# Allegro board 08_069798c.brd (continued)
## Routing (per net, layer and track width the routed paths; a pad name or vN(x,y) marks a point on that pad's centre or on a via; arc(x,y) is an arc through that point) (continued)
DA_P: length 65.8
  TOP w0.127: v1(73.97,33.04) 73.7,32.77 73.31,32.77 71.96,34.11 71.53,34.11 71.34,34.3 U8.C7
  L3_PRIMARY_POWER w0.127: v1(88.05,48.75) 88.39,48.41 88.39,46.38 89.15,45.62 95.89,45.62 96.5,45.01 96.5,42.1 96.02,41.62 92.58,41.62 92.29,41.33 92.29,40.13 92.58,39.84 95.04,39.84 95.95,38.93 95.95,36.58 94.14,34.77 90.23,34.77 88.54,36.46 86.61,36.46 86.19,36.04 86.19,34.82 87.88,33.13 87.88,32.7 87.75,32.57 87.38,32.57 v2(86.55,33.4) 85.61,32.46 81.23,32.46 80.91,32.14 78.51,32.14 77.95,32.7 74.31,32.7 v1(73.97,33.04)
  BOTTOM w0.127: v1(88.05,48.75) 88.39,49.09 88.39,49.73 90,51.35 91.12,51.35 91.24,51.47 P3.H7
DB_N: length 45
  L3_PRIMARY_POWER w0.127: v1(93.5,47.54) 93.84,47.88 93.84,48.06 93.71,48.18 90.39,48.18 89.25,49.32 87.41,49.32 85.97,47.89 85.97,45.26 86.15,45.09 87,45.09 88.41,43.68 88.41,43.19 87.84,42.61 87.5,42.61 v2(86.55,41.66) 85.59,42.61 83.82,42.61 82.95,41.74 79.65,41.74 79.04,41.13 79.04,35.55 78.09,34.59 74.34,34.59 v1(74.02,34.27)
  BOTTOM w0.127: P3.G10 92.51,48.4 92.64,48.53 93.67,48.53 93.83,48.36 93.83,47.87 v1(93.5,47.54) ; v1(74.02,34.27) 73.71,34.59 72.12,34.59 71.37,33.84 70.95,33.84 70.77,33.66 v2(70.32,33.66)
DB_P: length 45.9
  L3_PRIMARY_POWER w0.127: v1(94.46,47.56) 94.12,47.9 94.12,48.17 93.83,48.46 90.51,48.46 89.37,49.6 87.29,49.6 85.69,48.01 85.69,45.15 86.03,44.81 86.89,44.81 88.13,43.56 88.13,43.31 87.75,42.93 87.47,42.93 v2(86.55,43.85) 85.59,42.89 83.71,42.89 82.84,42.02 79.53,42.02 78.76,41.25 78.76,35.66 77.97,34.87 74.34,34.87 v1(74.02,35.19)
  BOTTOM w0.127: v1(94.46,47.56) 94.11,47.91 94.11,48.48 93.78,48.81 92.64,48.81 92.51,48.93 P3.G9 ; v2(70.32,34.3) 70.77,34.3 70.95,34.12 71.25,34.12 72,34.87 73.71,34.87 v1(74.02,35.19)
DCO_N: length 45.7
  L3_PRIMARY_POWER w0.127: v1(68.88,44.88) 69.2,45.2 69.2,46.24 69.82,46.85 69.82,51.48 71.45,53.11 74.02,53.11 75.18,51.95 78.22,51.95 78.87,52.6 80.27,52.6 84.25,56.58 87.56,56.58 89.76,54.38 91.26,54.38 91.54,54.66 91.54,55.32 91.41,55.45 90.85,55.45 90.7,55.3 v1(90.7,54.93)
  BOTTOM w0.127: v2(69.02,34.95) 69.02,35.4 69.2,35.59 69.2,44.55 v1(68.88,44.88)
  BOTTOM w0.203: P3.H5 v1(90.7,54.93)
DCO_P: length 46.1
  L3_PRIMARY_POWER w0.127: v1(69.83,44.88) 69.48,45.23 69.48,46.12 70.1,46.74 70.1,51.37 71.56,52.83 73.91,52.83 75.07,51.67 78.34,51.67 78.99,52.32 80.39,52.32 84.36,56.3 87.45,56.3 89.64,54.1 91.37,54.1 91.82,54.55 91.82,55.44 91.53,55.73 90.82,55.73 90.7,55.86 v1(90.7,56.2)
  BOTTOM w0.127: v1(69.83,44.88) 69.48,44.53 69.48,35.59 69.67,35.4 v2(69.67,34.95)
  BOTTOM w0.203: P3.H4 v1(90.7,56.2)
DOA: length 4.8
  TOP w0.203: JP10.2 84.64,34.26 84.84,34.47 87.53,34.47 87.94,34.87 U4.4
DOA_FMC: length 14.8
  TOP w0.203: U4.3 v1(86.99,35.29)
  L3_PRIMARY_POWER w0.127: v1(86.99,35.29) 87.42,34.86 87.42,34.53 89.68,32.27 92.58,32.27 92.99,32.68 93.49,32.68 96.2,35.38 96.75,35.38 96.87,35.51 v1(96.87,35.88)
  BOTTOM w0.203: P3.D20 v1(96.87,35.88)
DOB: length 4.2
  TOP w0.203: JP11.2 88.45,30.04 88.26,29.85 86.23,29.85 86.04,29.66 U5.4
DOB_FMC: length 14.6
  TOP w0.203: U5.3 v1(86.99,29.22)
  L3_PRIMARY_POWER w0.127: v1(86.99,29.22) 87.49,29.72 87.49,29.89 89.58,31.99 92.69,31.99 93.1,32.4 93.61,32.4 96.31,35.1 96.75,35.1 96.87,34.98 v1(96.87,34.61)
  BOTTOM w0.203: P3.D21 v1(96.87,34.61)
DOC: length 5.2
  TOP w0.203: JP12.2 84.64,44.86 84.87,45.09 87.75,45.09 87.94,45.27 U6.4
DOC_FMC: length 15.8
  TOP w0.203: U6.3 v1(86.99,45.96)
  L3_PRIMARY_POWER w0.127: v1(93.94,37.71) 93.6,37.38 93.02,37.38 90.06,40.33 90.06,42.65 89.77,42.94 89.28,42.94 89.15,43.07 89.15,44.58 87.77,45.96 v1(86.99,45.96)
  BOTTOM w0.127: P3.G18 92.51,37.5 92.64,37.38 93.6,37.38 v1(93.94,37.71)
DOD: length 4.2
  TOP w0.203: U7.4 86.04,40.2 86.23,40.39 88.18,40.39 88.45,40.65 JP13.2
DOD_FMC: length 15.6
  TOP w0.203: U7.3 v1(86.99,39.64)
  L3_PRIMARY_POWER w0.127: v1(93.94,36.76) 93.6,37.1 92.91,37.1 89.78,40.22 89.78,42.53 89.66,42.66 89.28,42.66 89.15,42.53 89.15,41.4 87.39,39.64 v1(86.99,39.64)
  BOTTOM w0.127: P3.G19 92.51,36.97 92.64,37.1 93.6,37.1 v1(93.94,36.76)
EC0: length 1.9
  BOTTOM w0.203: C70.1 74.41,58.28 74.25,58.11 U20.5
EC1: length 2.1
  BOTTOM w0.203: C69.1 74.25,51.54 U20.14
EN1V1: length 7.5
  TOP w0.203: 14.52,51.16 14.53,51.16 14.53,46.6 P5.2 ; 14.52,51.16 R20.2 ; 14.52,51.16 14.52,51.96 U35.4
EN_AFE: length 127.4
  TOP w0.203: U27.2 v1(18.85,14.72) ; U25.1 65.66,17.32 v1(66.85,17.32) 67.67,17.32 68.24,16.75 68.24,12.05 67.74,11.54 v1(66.78,11.54) 65.67,11.54 U36.3 ; U26.2 v1(14.28,14.77) ; U3.12 38.15,33.77 v1(38.41,34.04) ; v1(70.72,23.86) 69.7,23.86 U39.5 ; U28.1 v1(22.76,14.84) ; U23.4 77.84,4.78 78.31,4.3 79.23,4.3 80.13,5.21 v1(80.13,9)
  L3_PRIMARY_POWER w0.203: v1(70.72,23.86) 70.72,21.19 v1(66.85,17.32)
  BOTTOM w0.203: v1(66.78,11.54) 67.41,11.54 68.82,10.13 68.82,9.3 70.56,7.55 72.9,7.55 73.63,8.29 73.85,8.29 74.56,9 v1(80.13,9) ; v1(70.72,23.86) 66.59,23.86 59.93,30.53 47.57,30.53 P2.4 43.34,33.02 42.32,34.04 v1(38.41,34.04) 38.41,32.99 41,30.4 41,25.91 40.8,25.7 39.85,25.7 39.85,25.7 39.39,25.7 39.38,25.7 30.72,25.7 27.92,22.91 27.92,20.56 26.14,18.78 23.73,18.78 23.48,18.53 23.48,15.55 v1(22.76,14.84) 22.71,14.84 22.08,14.21 19.36,14.21 v1(18.85,14.72) 16.43,14.72 16.05,14.34 14.72,14.34 v1(14.28,14.77)
EN_PSU: length 77
  TOP w0.203: v1(90.48,36.49) 89.9,35.91 89.9,32.62 91.43,31.09 91.43,25.78 84.44,18.78 v1(84.44,18.21)
  L5_SECONDARY_POWER w0.203: v1(38.47,18.59) 38.47,20.76 39.73,22.02 41.83,22.02 43.67,20.18 50.38,20.18 50.7,20.5 51.67,20.5 52.06,20.11 82.53,20.11 v1(84.44,18.21)
  BOTTOM w0.203: P3.H19 90.89,36.6 90.78,36.49 v1(90.48,36.49)
  BOTTOM w0.254: U38.2 83.23,18.52 R133.2 83.68,18.21 v1(84.44,18.21)
  BOTTOM w0.508: v1(38.47,18.59) U19.3
EN_V33: length 33.1
  TOP w0.203: U24.4 72.76,4.05 70.47,1.76 58.97,1.76 55.8,4.94 55.8,8.4 v1(58.42,11.02) ; v1(59.8,14.72) 58.52,14.72 U21.4
  L3_PRIMARY_POWER w0.203: v1(58.42,11.02) 59.8,12.4 v1(59.8,14.72)
EN_VDDLDO: length 8
  TOP w0.203: P12.2 28.56,50.97 R19.2 27.8,51.36 28.28,51.84 U33.4
ENS1N: length 6.6
  TOP w0.203: U27.4 v1(19.5,18.16) ; U2.5 v1(17.59,21.78)
  BOTTOM w0.203: v1(19.5,18.16) 18.88,18.78 18.02,18.78 17.59,19.21 v1(17.59,21.78)
ENS1P: length 23
  TOP w0.203: U1.5 v1(17.59,37.02) ; U26.4 v1(14.93,18.21)
  BOTTOM w0.203: v1(14.93,18.21) 14.93,19.32 13.32,20.94 13.32,27.73 17.59,32.01 v1(17.59,37.02)
ENS3: length 55.4
  TOP w0.203: A1.8 56.04,41.83 v1(56.74,42.53) ; A6.8 55.8,27.57 v1(55.8,28.32) ; U28.4 v1(24.06,18.16)
  L3_PRIMARY_POWER w0.203: v1(55.8,28.32) 55.48,28.64 55.48,42.14 55.87,42.53 v1(56.74,42.53)
  BOTTOM w0.203: v1(24.06,18.16) 26.1,18.16 28.37,20.43 28.37,22.72 30.84,25.19 41.13,25.19 42.72,26.78 48.88,26.78 50.41,28.32 v1(55.8,28.32)
ENVIO: length 2.3
  TOP w0.203: R35.2 41.95,50.9 42.88,51.84 U34.4
EXT_5V: length 5.7
  TOP w0.508: P8.1 28.87,5.48 ; P8.1 27.63,4.24 ; P8.1 28.87,2.99
  BOTTOM w0.508: JP24.1 29.38,15.16 27.88,15.16 v1(27.73,15.01)
  vias: v1(25.33,10.1) v1(25.33,9.33) v1(25.33,8.57) v1(25.97,10.1) v1(25.97,9.33) v1(25.97,8.57) v1(26.6,10.1) v1(26.6,9.33) v1(26.6,8.57)
EXT_M2V5: length 6.9
  TOP w0.508: 33.02,5.17 P8.3 ; P8.3 33.02,3.31 ; P8.3 34.89,3.31 ; P8.3 34.89,5.17
  BOTTOM w0.508: JP25.1 29.34,19.82 v1(29.07,19.82)
  vias: v1(35.36,10.1) v1(35.36,9.33) v1(35.36,8.57) v1(36,10.1) v1(36,9.33) v1(36,8.57) v1(36.63,10.1) v1(36.63,9.33) v1(36.63,8.57)
EXT_VDD1V1: length 1.8
  TOP w0.635: 30.78,64.82 30.78,63.04
EXT_VDD3V3: length 3.5
  TOP w0.508: P11.1 43.61,5.74 ; P11.1 42.43,4.56 ; P11.1 43.61,3.38
EXT_VDDLDO: length 1.8
  TOP w0.762: 35.86,64.82 35.86,63.04
EXT_VIO1V1: length 1.8
  TOP w0.762: P4.1 40.94,63.04
FDA5: length 4.3
  TOP w0.203: U3.5 35,30.94 v1(34.67,30.61)
  BOTTOM w0.508: v1(34.67,30.61) 34.68,30.59 R125.1
FDA8: length 6.1
  TOP w0.203: v1(36.83,30.61) 36.5,30.94 U3.8
  BOTTOM w0.508: v1(36.83,30.61) 37.8,30.61 38.98,29.43 38.98,28.28 R127.1
FDA13: length 4.1
  TOP w0.203: U3.13 36.5,35.1 v1(36.83,35.43)
  BOTTOM w0.508: v1(36.83,35.43) 36.83,37.66 R126.1
FDA16: length 4.4
  TOP w0.203: U3.16 35,35.1 v1(34.67,35.43)
  BOTTOM w0.508: R124.1 33.68,36.17 34.42,35.43 v1(34.67,35.43)
FDA_OB_N: length 2.5
  TOP w0.203: R102.1 39.08,33.27 U3.11
FDA_OB_P: length 2.6
  TOP w0.203: R103.1 38.99,32.77 U3.10
FDA_ON: length 37.7
  TOP w0.203: JP17.1 60.12,39.66 60.12,43.29 58.44,44.97 55.71,44.97 53.39,47.29 51,47.29 JP15.3 46.51,44.55 45.08,43.11 P2.1 43.81,40.64 43.23,40.05 43.23,34.3 42.74,33.82 C75.1 42.14,33.24 41.65,33.24 41.28,33.62 R102.2 R33.2
FDA_OP: length 33.2
  TOP w0.203: R18.2 R103.2 41.28,32.39 41.73,32.84 42.1,32.84 C75.2 42.74,32.22 43.23,31.74 43.23,26.08 43.91,25.4 P2.7 46.72,27.04 46.72,29.46 47.58,30.32 JP16.3 48.31,30.32 50.54,32.56 56.37,32.56 59.61,29.32 JP18.1
FFB: length 3.9
  TOP w0.203: R119.2 C122.1 60.93,48.59 60.7,48.81 R122.1
FMC_VADJ: length 34.7
  TOP w0.254: v1(89.8,27.93) C81.1 U5.1 ; v1(84.18,47.26) C82.1 U6.1 ; U24.5 73.87,6.47 73.9,6.5 C56.1 74.02,6.56 v1(74.02,7.35) ; v1(75.37,53.44) 75.37,52.88 C72.1 ; U26.5 v1(13.63,18.18) ; U27.5 v1(18.2,18.13) ; v1(67.97,57.28) R71.1 ; U28.5 v1(22.76,18.13) ; 84.7,36.59 C80.1 U4.1 ; U7.1 C83.1 v1(89.8,38.34) ; 78,6.63 U23.5
  TOP w0.305: v1(79.11,7.41) 79.17,7.36 C55.1 78.05,6.69 78,6.63 ; U9.6 C3.1 77.8,46.56 77.8,46.74 77.99,46.94 78.57,46.94 78.72,46.78 v1(78.85,46.78) ; v1(84.04,36.59) 84.7,36.59
  TOP w0.508: v1(69.32,4.05) R16.1 ; R55.1 v1(16.11,16.55) ; R56.1 v1(20.68,16.55) ; v1(71.86,8.55) R47.1 ; R53.1 v1(11.54,16.6) ; v1(73.53,9.07) R46.1
  L5_SECONDARY_POWER w0.508: P7.1 4.36,16.81 ; P7.1 2.59,15.04 ; P7.1 2.59,16.81 ; P7.1 4.36,15.04
  BOTTOM w0.203: P3.H40 v1(90.7,9.38) ; P3.G39 v1(91.97,10.65)
  BOTTOM w0.254: U11.5 v1(81.58,22.29) ; U12.5 v1(81.58,25.96) ; U20.6 v1(75.7,57.44) ; U20.13 v1(75.37,53.44) ; U13.5 v1(81.58,29.64)
  BOTTOM w0.508: R72.1 77.77,56.95 v1(77.77,57.64) ; v1(77.71,53.26) 77.71,53.92 R74.1
  vias: v1(79.91,42.63) v1(79.91,30.57) v1(80.29,46.31) v1(80.29,45.8) v1(80.29,38.95) v1(80.29,38.45) v1(80.29,35.28) v1(80.29,34.77) v1(80.29,27.41) v1(80.29,26.9) v1(80.29,23.73) v1(80.29,23.23) v1(80.42,42.63) v1(80.42,30.57)
FPGACLK_N: length 27
  L3_PRIMARY_POWER w0.127: v1(93.06,57.47) 93.06,57.84 92.94,57.96 91.12,57.96 89.25,59.83 86.52,59.83 85.01,58.32 76.54,58.32 74.17,60.68 73.27,60.68 73.14,60.55 73.14,60.28 v1(73.47,59.94)
  BOTTOM w0.127: v1(73.47,59.94) 73.14,59.61 73.14,58.33 73.25,58.22 U20.3 ; P3.G3 v1(93.06,57.47)
FPGACLK_P: length 27.5
  L3_PRIMARY_POWER w0.127: v1(93.06,58.74) 93.06,58.37 92.94,58.24 91.23,58.24 89.37,60.11 86.4,60.11 84.89,58.6 76.65,58.6 74.29,60.96 73.15,60.96 72.86,60.67 72.86,60.28 v1(72.52,59.94)
  BOTTOM w0.127: U20.2 72.75,58.22 72.86,58.33 72.86,59.61 v1(72.52,59.94) ; P3.G2 v1(93.06,58.74)
GA0: length 11.7
  TOP w0.203: v1(98.14,17) 97.58,16.44 97.58,13 97.14,12.56 96.72,12.56 96.02,11.86 93.61,11.86 93.02,12.44 U18.2
  BOTTOM w0.203: P3.C34 v1(98.14,17)
GA1: length 9.4
  TOP w0.203: v1(96.87,15.73) 96.87,16.29 96.66,16.5 91.8,16.5 91.41,16.1 91.41,15.01 91.75,14.67 U18.1
  BOTTOM w0.203: P3.D35 v1(96.87,15.73)
GP0_DIR: length 10.7
  BOTTOM w0.178: U14.5 81.58,41.02 81.81,41.25 85.4,41.25 86.23,40.42 91.23,40.42 P3.H16
GP1_DIR: length 25.9
  BOTTOM w0.178: U15.5 81.58,44.7 81.83,44.94 83.29,44.94 83.74,44.5 87.42,44.5 87.76,44.16 89.05,44.16 90.98,46.09 91.65,46.09 91.83,45.91 91.83,45.35 92.3,44.88 94.28,44.88 95.47,46.07 96.57,46.07 96.91,45.73 96.91,45.35 97.38,44.88 98.66,44.88 99.33,44.21 99.33,42.06 98.95,41.68 P3.C15
GP2_DIR: length 19.9
  BOTTOM w0.178: U16.5 81.58,33.66 81.74,33.83 84.05,33.83 84.25,34.02 87.1,34.02 89.01,35.93 89.01,36.78 90.35,38.11 90.35,38.24 90.56,38.45 91.55,38.45 91.83,38.73 91.83,39.32 92.3,39.79 94.04,39.79 94.22,39.97 94.22,41.32 93.86,41.68 P3.G15
GP3_DIR: length 12.2
  BOTTOM w0.178: U17.5 81.58,37.34 81.81,37.57 84.16,37.57 84.82,36.91 87.2,36.91 88.95,38.66 88.95,39.13 89.47,39.66 90.16,39.66 90.68,39.14 P3.H17
GPIO0: length 19.5
  TOP w0.178: U8.G7 71.11,31.84 71.36,31.84 71.67,31.53 v1(71.67,31.16)
  BOTTOM w0.178: U14.4 82.23,40.1 82.05,39.93 81.38,39.93 81,39.55 79.61,39.55 79.36,39.29 79.36,35.99 78.85,35.48 78.85,32.56 77.58,31.29 72.37,31.29 72.25,31.16 v1(71.67,31.16)
GPIO0_FMC: length 9.8
  BOTTOM w0.178: U14.3 88.34,42.37 90.19,44.22 P3.H13
GPIO1: length 20.5
  BOTTOM w0.178: U15.4 82.09,44.01 82.09,43.82 81.82,43.56 81.34,43.56 81.14,43.36 79.61,43.36 79.23,42.97 79.23,39.7 78.98,39.45 78.98,36.15 77.04,34.21 74.9,34.21 74.33,33.64 73.26,33.64 72.63,33.01 v2(70.32,33.01)
GPIO1_FMC: length 21.1
  BOTTOM w0.178: U15.3 82.9,46.05 84.01,44.94 86.66,44.94 87.13,45.41 89.77,45.41 90.6,46.24 90.6,47.03 90.99,47.42 91.42,47.42 91.87,46.98 91.87,46.53 92.22,46.18 94.21,46.18 95.11,47.07 95.11,48.3 95.42,48.61 96.57,48.61 97.01,48.17 97.01,47.79 97.59,47.2 P3.C11
GPIO2: length 22.2
  TOP w0.178: v1(65.9,32.05) 65.93,32.09 66.79,32.09 66.87,32.17 66.89,32.17 U8.F1
  BOTTOM w0.178: v1(65.9,32.05) 67.1,32.05 67.29,31.86 67.29,29.67 68.01,28.96 74.29,28.96 75.86,30.53 78.02,30.53 79.8,32.31 81.96,32.31 82.23,32.58 U16.4
GPIO2_FMC: length 30.8
  L3_PRIMARY_POWER w0.178: v1(88.63,37.39) 90.56,37.39 91.9,36.05 94.41,36.05 94.91,36.56 94.91,38.28 94.6,38.59 92.82,38.59 91.3,40.12 91.3,43.04 91.93,43.67 94.41,43.67 v1(95.73,42.35)
  BOTTOM w0.178: v1(88.63,37.39) 88.63,36.08 86.95,34.4 84.5,34.4 83.89,35.02 U16.3 ; P3.D14 v1(95.73,42.35)
GPIO3: length 22.2
  BOTTOM w0.178: U17.4 82.23,36.42 82.05,36.24 81.38,36.24 81.13,35.99 79.99,35.99 79.23,35.23 79.23,32.37 77.77,30.91 75.71,30.91 74.13,29.34 68.17,29.34 67.72,29.78 v2(67.72,32.36)
GPIO3_FMC: length 25.7
  BOTTOM w0.178: P3.D15 96.32,42.12 96.91,42.71 96.91,43.19 96.46,43.64 90.24,43.64 89.9,43.29 89.9,41.26 90.16,40.99 91.49,40.99 91.83,40.65 91.83,40.07 91.49,39.72 90.99,39.72 90.67,40.04 89.32,40.04 88.5,39.23 88.5,38.78 87.01,37.29 84.98,37.29 84.32,37.95 83.86,37.95 83.11,38.69 U17.3
IN+: length 6.8
  TOP w0.127: U8.D1 66.7,33.66 66.5,33.45 64.84,33.45 C36.2 64.5,33.77 64.08,33.35 63.78,33.35 63.13,34 C35.2 62.39,33.28 62.19,33.28 61.67,33.81 R32.2
IN-: length 6.6
  TOP w0.127: U8.E1 66.7,33.01 66.54,33.17 64.85,33.17 64.5,32.81 C37.1 64.22,33.07 63.77,33.07 C35.1 63.01,32.4 62.4,33.01 62.15,33.01 61.67,32.52 R88.2
IOVDD: length 6.5
  TOP w0.203: v1(83.22,13.4) 82.65,13.97 A3.3
  TOP w0.254: U8.A6 v1(70.32,36.12)
  BOTTOM w0.508: P10.2 76.07,40.32 ; P10.2 74.39,40.32 ; P10.2 74.39,38.64 ; P10.2 76.07,38.64
  vias: v1(70.32,36.62) v1(70.83,36.62)
LDO_IN_VDD1V1:
  vias: v1(13.84,53.47) v1(13.84,52.83) v1(14.47,53.47) v1(14.47,52.83) v1(19.81,49.53) v1(19.81,48.83) v1(20.44,49.53) v1(20.44,48.83) v1(28.06,58.04) v1(28.06,57.34) v1(28.7,58.04) v1(28.7,57.34)
LDO_IN_VDD3V3: length 14.2
  TOP w0.203: 54.4,16.88 54.27,16.75 U21.7
  TOP w0.508: 54.21,17.26 54.31,17.36 R91.2
  TOP w0.635: R34.2 45.87,11.99 46.66,11.99 48.47,13.8 48.47,15.61 50.07,17.2 50.07,17.31 v1(52.05,17.31)
  vias: v1(52.05,18.02) v1(52.88,18.02) v1(52.88,17.31) v1(61.15,13.23) v1(61.15,12.73) v1(61.65,13.23) v1(61.65,12.73)
LDO_IN_VDDLDO:
  vias: v1(27.87,53.34) v1(27.87,52.7) v1(28.51,53.34) v1(28.51,52.7) v1(33.08,58.04) v1(33.08,57.34) v1(33.71,58.04) v1(33.71,57.34) v1(33.7,49.39) v1(33.7,48.63) v1(34.34,49.39) v1(34.34,48.63)
LDO_IN_VIO1V1:
  vias: v1(38.29,58.1) v1(38.29,57.4) v1(38.92,58.1) v1(38.92,57.4) v1(41.59,53.34) v1(41.59,52.7) v1(42.22,53.34) v1(42.22,52.7) v1(47.35,49.39) v1(47.35,48.69) v1(47.99,49.39) v1(47.99,48.69)
NEG_5V0: length 12.7
  BOTTOM w0.254: C26.2 82.12,20.15 81.58,19.6 U38.12 81.58,18.52 v1(81.33,18.27)
  BOTTOM w0.508: U19.2 C118.1 40.47,20.75 ; R138.2 82.47,14.46 81.81,15.13 C27.2 ; R138.2 v1(81.29,14.25) ; R138.2 82.47,13.51 81.83,12.88 C29.2 ; v1(76.75,16.11) 77.73,16.11 R137.2
  vias: v1(41.28,21.02) v1(41.28,20.38) v1(41.92,21.02) v1(41.9,20.37)
OSC_EN: length 89.4
  TOP w0.178: v1(59.88,48.58) 59.88,51.69 60.2,52.01 U30.4 ; v1(93.21,40.76) 92.11,41.86 92.11,50.2 89.83,52.48 v1(89.83,58.09) ; v1(58.29,65.16) R61.2 57.11,64.39 Y1.1
  BOTTOM w0.178: v1(58.29,65.16) 54.76,61.63 54.38,61.63 53.13,60.39 53.13,48.97 54.22,47.88 56.95,47.88 57.25,47.59 58.88,47.59 v1(59.88,48.58) 62.35,48.58 63.07,47.86 79.48,47.86 82.41,50.79 86.56,50.79 89.45,53.67 89.45,57.71 v1(89.83,58.09) ; P3.G16 92.87,40.76 v1(93.21,40.76)
OUT_VDDLDO: length 3.6
  L5_SECONDARY_POWER w0.508: 40.92,47.31 P6.1 ; P6.1 42.61,47.31 ; P6.1 42.61,45.63
  vias: v1(35.75,58.04) v1(35.75,57.34) v1(36.38,58.04) v1(36.38,57.34)
P1N: length 4.8
  TOP w0.203: U27.1 R55.2 16.82,14.96 17.03,14.75 17.47,14.75 18.09,14.13 S1.2B
P1P: length 8.4
  TOP w0.203: S1.1B 16.82,13.75 16.57,14.01 12.5,14.01 12.25,14.26 R53.2 U26.1
P1S1: length 2.5
  BOTTOM w0.635: JP19.2 P1.3
P1S2: length 2.5
  BOTTOM w0.635: JP20.2 P1.5
P3: length 6.3
  TOP w0.203: S1.3B 19.36,13.65 21.26,15.55 R56.2 21.48,15.55 22.04,16.11 23.21,16.11 23.41,15.91 U28.2
PBIO<0>: length 109.7
  BOTTOM w0.178: P7.2 9.71,12.23 14.03,12.23 14.81,11.46 37.38,11.46 39.89,8.94 48.78,8.94 50.88,6.84 69.32,6.84 69.39,6.78 82.91,6.78 85.1,8.96 85.1,10.12 86.91,11.93 86.91,22.4 88,23.49 88,27.74 88.4,28.14 88.4,30.08 89.84,31.52 P3.H23
PBIO<1>: length 119.2
  BOTTOM w0.178: P3.G21 92.51,33.65 91.89,33.03 91.89,32.56 91.48,32.14 89.92,32.14 88.02,30.24 88.02,28.39 87.61,27.99 87.61,23.73 86.53,22.65 86.53,12.09 84.72,10.28 84.72,9.12 82.82,7.22 80.15,7.22 79.38,7.99 76.13,7.99 75.78,7.63 75,7.63 74.74,7.9 73.8,7.9 73.06,7.16 69.54,7.16 69.48,7.22 51.04,7.22 48.94,9.32 40.05,9.32 37.53,11.84 14.96,11.84 10.99,15.81 7.81,15.81 6.34,17.27 5.01,17.27 4.69,16.95 4.69,14.6 P7.3
PBIO<2>: length 114.7
  BOTTOM w0.178: P3.G22 93.54,32.79 93.72,32.61 93.72,31.01 93.54,30.83 92.27,30.83 91.93,30.49 91.93,30.11 91.49,29.67 89.98,29.67 89.24,28.93 89.24,28.37 88.47,27.6 88.47,23.26 87.29,22.08 87.29,11.78 85.48,9.96 85.48,7.38 84.08,5.98 83.39,5.98 82.97,6.4 69.23,6.4 69.16,6.46 50.72,6.46 48.62,8.56 39.73,8.56 37.22,11.07 14.65,11.07 13.87,11.85 7.55,11.85 P7.4
PBIO<3>: length 112.9
  BOTTOM w0.178: P7.5 4.74,12.11 6.65,12.11 7.54,11.22 8.65,11.22 9.18,10.69 37.06,10.69 39.58,8.18 48.47,8.18 50.56,6.08 69.01,6.08 71.08,4.01 81.93,4.01 82.98,5.05 85.72,5.05 86.02,5.36 86.02,7.8 85.86,7.96 85.86,9.8 87.68,11.62 87.68,21.78 88.95,23.05 88.95,26.28 91.24,28.58 P3.H25
PBIO<4>: length 109.7
  BOTTOM w0.178: P7.6 8.49,10.84 9.05,10.29 22.57,10.29 25.06,7.8 48.31,7.8 50.4,5.7 68.85,5.7 70.95,3.59 74.03,3.59 74.97,2.66 84.19,2.66 88.12,6.59 88.12,21.69 89.33,22.9 89.33,26.12 90.62,27.42 90.95,27.42 P3.H26
PBIO<5>: length 116.4
  BOTTOM w0.178: P7.7 4.17,9 5.13,9 5.55,9.42 6.59,9.42 6.7,9.53 11.49,9.53 11.87,9.91 22.42,9.91 24.91,7.41 48.15,7.41 50.25,5.32 51.96,5.32 55,2.28 84.35,2.28 88.5,6.43 88.5,21.45 89.71,22.65 89.71,25.78 90.96,27.04 91.48,27.04 91.89,27.45 91.89,29.24 92.51,29.86 P3.G24
PBIO<6>: length 115.1
  BOTTOM w0.178: P7.8 6.86,9.14 11.29,9.14 12.13,8.3 23.48,8.3 24.75,7.03 47.99,7.03 50.09,4.94 51.8,4.94 54.84,1.9 84.51,1.9 88.88,6.27 88.88,21.18 90.09,22.39 90.09,24.31 90.33,24.55 93.47,24.55 93.72,24.8 93.72,27.77 P3.G25
PBIO<7>: length 121.2
  BOTTOM w0.178: P3.D23 94.36,29.55 94.36,22.99 93.35,21.98 90.62,21.98 89.26,20.62 89.26,6.11 84.67,1.52 52.54,1.52 47.41,6.65 24.59,6.65 23.32,7.92 8.68,7.92 7.74,6.99 4.7,6.99 P7.9
PBIO<8>: length 117.4
  BOTTOM w0.178: P7.10 7.66,5.76 9.44,7.54 23.16,7.54 24.43,6.27 47.25,6.27 52.38,1.14 84.83,1.14 89.64,5.95 89.64,18.77 90.66,19.79 90.66,20.53 90.84,20.71 93.1,20.71 94.76,22.38 94.76,28.69 P3.D24
PD_V33B: length 44.7
  TOP w0.203: U24.2 v1(70.1,5.82) 70.09,5.82 R16.2 ; v1(75.18,5.82) U23.2 76.81,5.82 77.01,6.02 77.01,6.85 79.8,9.64 82.77,9.64 88.02,14.88 88.02,19.7 91.82,23.49 91.82,32.21 91.23,32.79 v1(90.57,32.79)
  BOTTOM w0.203: P3.H22 v1(90.57,32.79)
  BOTTOM w0.254: v1(70.1,5.82) v1(75.18,5.82)
PG_C2M: length 152.2
  TOP w0.203: U31.3 v1(86.79,59.31) 92.26,59.31 92.69,59.74 93.33,59.74 94.52,58.55 v1(94.99,58.55) 95.55,57.99 95.55,57.33 96.5,56.37 99.99,56.37 102.03,54.34 102.03,12.01 97.68,7.66 94.48,7.66 92.2,9.94 90.14,9.94 88.63,8.43 88.63,6.27 86.86,4.51 v1(83.62,4.51) 82.76,4.51 R43.2 82.73,4.56 A4.1 ; v1(78.4,10.46) 78.4,11.3 R44.2 78.4,12.5 A2.1 ; U32.3 v1(86.1,53.53)
  L3_PRIMARY_POWER w0.203: v1(83.62,4.51) 81.45,6.68 81.45,10.27 80.63,11.1 79.04,11.1 v1(78.4,10.46)
  BOTTOM w0.203: P3.D1 95.41,58.55 v1(94.99,58.55) ; v1(86.79,59.31) 86.46,58.98 85.93,58.98 85.07,58.12 85.07,54.56 v1(86.1,53.53) ; R24.1 46.97,12.11 67.48,12.11 69.26,10.34 69.26,9.43 70.73,7.96 72.35,7.96 72.82,8.43 72.82,9.19 73.69,10.07 74.51,10.07 74.62,9.95 77.9,9.95 v1(78.4,10.46)
PMSEL: length 25.5
  TOP w0.508: S1.4B R54.1 21.9,13.62 22.41,14.13 30,14.13 30.78,14.91 30.78,25.26 v1(32.88,27.35)
  BOTTOM w0.508: v1(32.88,27.35) 33.64,27.35 R125.2
PWRGD: length 59.7
  TOP w0.178: R46.2 v1(75.23,8.18) R85.1 75.94,7.29 75.94,7.29 U23.1 ; v1(79.8,41.13) 78.98,41.96 78.98,43.2 U9.3 ; v1(90.64,35.33) 91.32,35.33 92.18,34.47 92.18,23.34 88.39,19.54 88.39,14.73 81.47,7.81 v1(80.83,7.81) A4.4
  L3_PRIMARY_POWER w0.178: v1(90.64,35.33) 90.18,35.33 88.67,36.84 88.4,36.84 87.79,37.45 86.91,37.45 86.91,37.51 83.29,41.13 v1(79.8,41.13)
  BOTTOM w0.178: P3.H20 v1(90.64,35.33) ; v1(75.23,8.18) 75.48,8.43 79.58,8.43 80.2,7.81 v1(80.83,7.81)
REF: length 32.7
  TOP w0.305: v2(69.02,31.71) v2(69.02,32.36)
  TOP w0.432: v2(69.02,31.71) v1(69.02,30.92) v1(69.02,30.42)
  TOP w0.508: v1(70.15,22.15) 70.15,21.37 JP2.2
  L5_SECONDARY_POWER w0.305: v1(37.11,26.57) 39.14,24.54 41.09,24.54 41.58,24.05 57.83,24.05
  L5_SECONDARY_POWER w0.508: 58.32,21.69 REF.1 ; REF.1 60.01,21.69 ; REF.1 60.01,23.37 ; REF.1 58.32,23.37
  BOTTOM w0.305: v1(69.02,30.42) 69.02,30.04 C43.1
  BOTTOM w0.432: v1(69.02,30.42) v1(69.02,30.92) v2(69.02,31.71) v2(69.02,32.36)
  BOTTOM w0.508: R127.2 v1(37.11,26.57)
  vias: v1(67.81,26.5) v1(67.81,26) v1(68.32,26.5) v1(68.32,26) v1(69.34,26.5) v1(69.34,26) v1(69.72,31.08) v1(69.72,30.57) v1(69.84,26.5) v1(69.84,26) v1(70.23,31.08) v1(70.23,30.57)
REF3S: length 1.8
  TOP w0.305: R146.1 72.02,11.57 U36.6
REFBUF_IN: length 7.6
  TOP w0.508: JP1.3 66.78,19.35 R148.1 R149.1
REFBUF_OUT: length 1.3
  TOP w0.508: R151.2 JP2.1
REFCLK: length 4.3
  TOP w0.203: U30.24 58.7,58.32 58.49,58.52 57.37,58.52 C127.1 55.31,59.45 C129.1
S1_OM: length 41.7
  TOP w0.203: v1(39.48,30.85) R18.1 ; R106.2 13.57,26.92 v1(14.46,26.92)
  TOP w0.508: R11.1 24.19,31.71 24.19,26.99 v1(22.72,25.51) R114.2 21.8,23.21 C32.1
  BOTTOM w0.203: v1(14.46,26.92) 15.87,25.51 v1(22.72,25.51) 28.94,31.74 38.59,31.74 v1(39.48,30.85)
S1_OP: length 42
  TOP w0.203: v1(39.48,35.1) R33.1 ; R52.2 v1(14.46,42.23)
  TOP w0.508: C31.2 R66.2 v1(22.65,40.64) 23.02,40.64 24.25,39.41 24.25,34.27 R10.1
  BOTTOM w0.203: v1(39.48,35.1) 38.97,34.59 38.18,34.59 37.8,34.21 34.43,34.21 34.38,34.16 33.91,34.16 33.86,34.21 28.78,34.21 22.65,40.34 v1(22.65,40.64) 16.05,40.64 v1(14.46,42.23)
SCK: length 15.3
  TOP w0.178: U8.E7 71.55,33.01 74.59,29.96 v1(76.25,29.96)
  BOTTOM w0.178: R111.2 83.1,28.93 U13.4 82.09,28.79 82.09,28.59 81.9,28.4 81.38,28.4 81.03,28.05 80.12,28.05 78.21,29.96 v1(76.25,29.96)
SCL: length 8.9
  TOP w0.178: v1(98.14,22.08) 98.14,22.47 97.5,23.11 95.34,23.11 94.29,22.07 U18.6
  BOTTOM w0.178: P3.C30 v1(98.14,22.08)
SCLK1: length 94.7
  TOP w0.178: v1(70.45,53.4) 68.51,53.4 68.07,52.96 68.07,47.37 67.11,46.42 60.42,46.42 57.21,49.63 57.21,51.24 58.7,52.73 U30.1
  BOTTOM w0.178: P3.D18 96.95,38.49 99.07,38.49 100.11,39.54 100.11,48.17 100.77,48.82 100.77,59.06 98.78,61.05 96.41,61.05 95.18,59.82 93.66,59.82 92.01,61.47 90.58,61.47 87.61,58.5 87.61,55.98 88.5,55.1 88.5,53.8 86.25,51.55 81.77,51.55 79.83,49.61 71.96,49.61 70.45,51.12 v1(70.45,53.4) 70.45,53.78 70.85,54.19 U20.19
SCLK_SRC: length 24.4
  BOTTOM w0.178: P3.H14 91.92,42.28 94.03,42.28 94.6,41.7 94.6,38.71 94.42,38.53 92.35,38.53 91.93,38.11 91.93,36.31 91.57,35.94 90.48,35.94 90.09,35.56 90.09,35.54 90.09,35.53 90.09,34.81 88.53,33.26 87.17,33.26 84.29,30.38 R111.1 83.1,30.83 U13.3
SDA: length 8.2
  TOP w0.178: v1(98.14,20.81) 98.14,21.29 97.47,21.97 97.47,22.28 97.1,22.64 95.77,22.64 95.56,22.44 U18.5
  BOTTOM w0.178: P3.C31 v1(98.14,20.81)
SDI: length 17.5
  TOP w0.178: v1(76.37,28.81) 75.17,28.81 71.63,32.36 U8.F7
  BOTTOM w0.178: v1(76.37,28.81) 77.13,28.81 79.61,26.34 79.61,24.64 79.79,24.46 81.12,24.46 81.38,24.72 81.87,24.72 81.88,24.74 81.89,24.74 82.09,24.93 82.09,25.11 U12.4 83.1,25.25 R110.2
SDIN1: length 87.9
  TOP w0.178: U30.2 59.2,52.46 58.03,51.3 v1(58.03,50.16)
  BOTTOM w0.178: 67.88,58.55 67.41,58.08 67.41,56.48 67.08,56.15 67.08,54.66 67.39,54.34 67.39,53.49 66.62,52.72 66.62,50.37 66.03,49.78 58.41,49.78 v1(58.03,50.16) ; 67.88,58.55 67.88,59.44 69.02,60.58 76.64,60.58 77.66,59.56 86.16,59.56 86.85,60.25 88.78,60.25 90.45,61.91 92.14,61.91 93.83,60.22 95.01,60.22 96.25,61.46 99.07,61.46 101.28,59.25 101.28,48.77 100.5,47.99 100.5,39.37 99,37.87 P3.C18 ; 67.88,58.55 68.86,58.55 69.39,58.02 70.12,58.02 70.29,57.85 70.29,57.43 71.04,56.69 U20.24
SDIO_SRC: length 37.2
  BOTTOM w0.178: P3.G13 94.45,44.22 95.11,44.88 96.73,44.88 96.91,44.7 96.91,44.08 97.35,43.64 98.74,43.64 98.95,43.42 98.95,42.44 98.78,42.26 97.35,42.26 97.01,41.92 97.01,41.32 96.78,41.1 95.51,41.1 95.05,40.64 95.05,36.43 94.55,35.93 92.28,35.93 91.83,35.47 91.83,35.09 91.4,34.66 90.47,34.66 88.63,32.81 87.29,32.81 85.39,30.91 85.39,27.29 84.8,26.7 R110.1 83.1,27.15 U12.3
SDO_1: length 62.7
  L3_PRIMARY_POWER w0.203: v1(73.75,58.4) 73.24,57.9 70.68,57.9 70.36,58.22 70.36,61.67 70.56,61.87 75.86,61.87 77.63,60.1 84.92,60.1 85.92,61.1 86.27,61.1 87.07,61.9 91.74,61.9 93.54,60.1 97.26,60.1 100.77,56.59 100.77,48.07 99.72,47.02 99.72,40.68 v1(98.85,39.82)
  BOTTOM w0.203: v1(73.75,58.4) U20.4 ; P3.D17 96.73,39.14 97.4,39.81 98.85,39.81 v1(98.85,39.82)
SNS33: length 57.1
  TOP w0.203: v1(49.86,10.68) 50.98,10.68 51.01,10.65 R132.2
  TOP w0.305: v2(68.37,32.36) v2(68.37,31.71)
  TOP w0.432: v2(68.37,31.71) v1(68.37,30.91) 68.37,30.41 v1(68.37,30.4) v1(68.37,29.9)
  TOP w0.508: R41.1 VDD33.1
  L4_GND w0.432: v2(68.37,32.36) v2(68.37,31.71) v1(68.37,30.91) 68.37,29.9 v1(68.37,29.9)
  L5_SECONDARY_POWER w0.508: v1(49.86,10.68) 50.85,9.7 58.98,9.7 59.25,9.43 61.37,9.43 61.89,9.95 73.72,9.95 74.1,10.34 75.29,10.34 75.92,9.71 80.43,9.71 80.44,9.7 83.68,9.7 84.24,9.14 VDD33.1
  BOTTOM w0.432: v2(68.37,32.36) v2(68.37,31.71) v1(68.37,30.91) 68.37,29.9 v1(68.37,29.9)
  BOTTOM w0.508: v1(42.67,11.37) 49.18,11.37 v1(49.86,10.68)
  vias: v1(42.03,12.06) v1(42.03,11.37) v1(42.67,12.06)
TMPC: length 2.8
  TOP w0.203: C140.1 62.64,59.27 C136.1 61.49,59.27 61.26,59.04 61.26,58.32 61.2,58.26 U30.19
UNNAMED_4_CMOSNC7SZ125_I71_Y: length 1.6
  TOP w0.203: U29.4 R60.1
UNNAMED_4_CN160PCDGHV2_I72_TDI: length 2.8
  TOP w0.508: v1(96.87,22.08) v1(96.87,20.81)
  BOTTOM w0.203: P3.D31 v1(96.87,20.81) ; P3.D30 v1(96.87,22.08)
UNNAMED_4_CN160PCDGHV2_I97_LA00NCC: length 4.5
  TOP w0.127: v1(95.1,53.62) 95.11,53.63 R40.2
  BOTTOM w0.127: v1(95.1,53.62) 94.76,53.29 94.76,52.5 94.47,52.21 92.88,52.21 P3.G7
UNNAMED_4_CN160PCDGHV2_I97_LA00PCC: length 4.2
  TOP w0.127: R39.2 94.15,54.24 v1(94.15,53.62)
  BOTTOM w0.127: P3.G6 93.14,52.49 94.36,52.49 94.48,52.62 94.48,53.29 v1(94.15,53.62)
UNNAMED_4_DIOLED_I76_P: length 1.5
  TOP w0.203: CNVEN.A 94.69,47.04 R60.2
UNNAMED_5_ADM108X_I2_ENIN: length 1.5
  TOP w0.203: R45.2 82.22,11.5 A3.1
UNNAMED_5_ADM108X_I19_VIN: length 2.8
  TOP w0.203: R41.2 R42.1 A4.3
UNNAMED_5_DIOLED_I115_P: length 1.3
  TOP w0.178: R85.2 DS1.A
UNNAMED_7_AD9508_I87_INSEL: length 2.6
  TOP w0.203: v1(69.75,57.27) 69.74,57.28 R71.2
  BOTTOM w0.203: v1(69.75,57.27) 69.73,57.27 70.81,56.19 U20.23
UNNAMED_7_ADF435X_I58_MUXOUT: length 1.9
  TOP w0.178: R123.1 56.38,54.69 U30.30
UNNAMED_7_ADF435X_I58_RFOUTA: length 2.8
  TOP w0.203: C138.1 64.65,56.07 L4.1 64.5,55.93 64.26,55.69 U30.13
UNNAMED_7_ADF435X_I58_RFOUTA_1: length 2.8
  TOP w0.203: C137.1 64.64,54.82 L3.1 64.27,55.19 U30.12
UNNAMED_7_ADF435X_I58_RSET: length 1.5
  TOP w0.203: U30.22 59.7,58.95 59.94,59.19 R121.1
UNNAMED_7_ADF435X_I58_SW: length 2
  TOP w0.203: R122.2 U30.5
UNNAMED_7_ADP7118V2_I95_SENSE: length 3.9
  TOP w0.178: R99.2 R98.1 C104.1 80.97,59.31 U31.4
UNNAMED_7_CAP_I6_N2: length 5.1
  TOP w0.178: C65.2 74.46,64.34 74.04,64.77 74.04,66.17 73.73,66.48 T1.5
UNNAMED_7_RES_I8_N1: length 9.3
  TOP w0.127: R68.1 69.63,56.07 69.76,55.94 69.76,55.71 69.88,55.58 70.29,55.58 70.42,55.71 70.42,60 R64.2 69.96,60.4 69.29,61.06 T1.3
UNNAMED_7_RES_I10_N1: length 9.7
  TOP w0.127: R65.1 69.63,54.82 69.76,54.95 69.76,55.18 69.88,55.3 70.41,55.3 70.7,55.59 70.7,59.99 R63.1 71.16,60.4 71.83,61.06 T1.1
UNNAMED_7_RES_I10_N2: length 1.1
  TOP w0.203: R63.2 R64.1
UNNAMED_8_ADA4899_I108_FEEDBACK: length 2
  TOP w0.203: A1.1 49.92,42.05 R17.2
UNNAMED_8_ADA4899_I108_INV: length 2
  TOP w0.203: A1.2 49.92,40.35 R17.1
UNNAMED_8_ADA4899_I108_NINV: length 2
  TOP w0.203: R58.2 48.55,39.29 A1.3
UNNAMED_8_ADA4899_I108_VOUT: length 1.8
  TOP w0.203: A1.6 56.85,39.29 56.85,39.29 R105.1
UNNAMED_8_ADA4899_I113_FEEDBACK: length 2
  TOP w0.203: R57.2 49.92,27.76 A6.1
UNNAMED_8_ADA4899_I113_INV: length 2
  TOP w0.203: R57.1 49.92,26.06 A6.2
UNNAMED_8_ADA4899_I113_NINV: length 2
  TOP w0.203: R59.2 48.55,25 A6.3
UNNAMED_8_ADA4899_I113_VOUT: length 1.8
  TOP w0.203: A6.6 56.85,25 56.85,25 R104.1
UNNAMED_8_ADA49451_I81_: length 4.2
  TOP w0.203: 33.07,31.29 33.38,31.61 33.38,31.99 33.66,32.27 U3.4
  TOP w0.508: R15.2 32.36,30.73 C18.2 33.07,31.29
UNNAMED_8_ADA49451_I81__1: length 4.2
  TOP w0.203: U3.1 33.66,33.77 33.38,34.05 33.38,34.43 33.07,34.75
  TOP w0.508: 33.07,34.75 C17.2 32.36,35.31 R14.2
UNNAMED_8_ADA49451_I81__2: length 3.5
  TOP w0.203: U3.3 32.95,32.77 C18.1
  TOP w0.508: R13.2 C18.1
UNNAMED_8_ADA49451_I81__3: length 3.5
  TOP w0.203: U3.2 32.95,33.27 C17.1
  TOP w0.508: R12.2 C17.1
UNNAMED_8_ADLT6236_I15_: length 3.3
  TOP w0.508: U2.3 15.28,25.4 C79.1 14.68,25.4 R6.2
UNNAMED_8_ADLT6236_I15__1: length 4.5
  TOP w0.254: 16.64,20.96 R9.1 U2.4 ; 16.64,20.96 15,20.96 R7.2 ; 16.64,20.96 v1(16.64,19.93)
UNNAMED_8_ADLT6236_I15_OUT: length 3.8
  TOP w0.254: R9.2 v1(18.34,19.93)
  TOP w0.381: v1(20.05,24.37) 20.05,25.36 20.09,25.4 19.99,25.4
  TOP w0.508: R114.1 19.99,25.4 U2.1
UNNAMED_8_ADLT6236_I33_: length 3.3
  TOP w0.508: U1.3 15.28,40.64 C67.1 14.68,40.64 R4.2
UNNAMED_8_ADLT6236_I33__1: length 4.5
  TOP w0.254: U1.4 R8.1 ; R8.1 R5.2 ; R8.1 v1(16.64,35.17)
UNNAMED_8_ADLT6236_I33_OUT: length 3.6
  TOP w0.254: R8.2 v1(18.34,35.17)
  TOP w0.381: U1.1 R66.1 20.05,40.6 v1(20.05,39.61)
UNNAMED_8_CAP_I54_N1: length 6.1
  TOP w0.305: C103.2 29.25,32.2 R13.1 ; C103.2 C16.1 ; C103.2 27.81,32.26 R11.2
  TOP w0.508: R15.1 R13.1
UNNAMED_8_CAP_I57_N2: length 6.1
  TOP w0.305: C103.1 29.28,33.81 R12.1 ; C103.1 27.84,33.78 R10.2 ; C103.1 C15.2
  TOP w0.508: R14.1 R12.1
UNNAMED_8_CAP_I93_N1: length 9.3
  TOP w0.203: C109.1 R58.1 47.49,37.3 47.29,37.5 47.29,43.1 47.73,43.55 JP15.2
UNNAMED_8_CAP_I115_N1: length 9.4
  TOP w0.203: JP16.2 47.58,29.32 47.29,29.03 47.29,23.21 47.49,23.01 R59.1 C92.1
UNNAMED_8_RES_I10_N1: length 10.9
  TOP w0.203: R5.1 15.16,37.89
  TOP w0.254: v1(15.89,37.32) 15.73,37.32 15.16,37.89
  L4_GND w0.254: v1(22.52,41.9) 22.52,41.34 22.07,40.88 22.07,40.68 19.92,38.53 16.17,38.53 15.93,38.29 15.93,37.53 15.73,37.32 v1(15.89,37.32)
UNNAMED_8_RES_I20_N1: length 9.6
  TOP w0.254: R78.1 22.98,24 22.84,23.86 v1(22.84,23.71) ; v1(15.88,22.68) R7.1
  L4_GND w0.254: v1(22.84,23.71) 21.93,23.71 20.49,22.27 17.92,22.27 17.83,22.36 17.35,22.36 17.26,22.27 16.14,22.27 15.88,22.53 v1(15.88,22.68)
UNNAMED_8_RES_I20_N2: length 1.7
  TOP w0.508: v1(23.79,24.15) 23.79,24.25 R78.2
  BOTTOM w0.508: v1(23.79,24.15) 25.06,24.15 JP14.2
UNNAMED_8_RES_I163_N1: length 2.6
  TOP w0.203: R70.1 61.67,36.28 61.01,36.94 JP17.2
UNNAMED_8_RES_I164_N1: length 1.5
  TOP w0.203: R76.1 JP18.2
UNNAMED_8_RES_I185_N2: length 1.8
  TOP w0.203: JP17.3 60,38.54 R105.2
UNNAMED_8_RES_I186_N2: length 4.3
  TOP w0.203: JP18.3 61.67,27.57 59.25,25.16 R104.2
UNNAMED_8_RES_I219_N1: length 1.5
  TOP w0.508: v1(23.54,41.9) 23.6,41.96 R29.1
  BOTTOM w0.508: JP7.2 24.81,41.9 v1(23.54,41.9)
UNNAMED_11_CAP_I205_N1: length 2.9
  TOP w0.203: C14.1 52.37,12.24 52.69,11.92
  TOP w0.508: C14.1 52.71,12.15 R132.1
UNNAMED_11_LINLT3045_I202_ILIM: length 1.7
  TOP w0.203: R108.1 59.84,15.98 U21.6
UNNAMED_11_LINLT3045_I202_SET: length 4
  TOP w0.305: U21.8 53.41,15.33 53.41,15.86 52.98,15.86 52.73,16.11 C46.1 52.66,15.92 52.6,15.86 52.6,14.53 R95.1
UNNAMED_11_LINLT3045_I215_ILIM: length 1.6
  TOP w0.203: R112.1 U33.6
UNNAMED_11_LINLT3045_I215_SET: length 3.5
  TOP w0.203: U33.8 35.96,51.19 R96.1 36.08,51.23 C86.1
UNNAMED_11_LINLT3045_I220_ILIM: length 1.6
  TOP w0.203: U35.6 R131.1
UNNAMED_11_LINLT3045_I220_SET: length 3.4
  TOP w0.305: C87.1 21.67,49.37 R107.1 21.21,51.25 20.98,51.25 20.92,51.31 U35.8
UNNAMED_11_LINLT3045_I229_ILIM: length 1.6
  TOP w0.203: R130.1 U34.6
UNNAMED_11_LINLT3045_I229_SET: length 3.5
  TOP w0.305: U34.8 49.32,51.19 R97.1 49.79,51.31 C45.1
UNNAMED_12_ADLT8604_I100_FB: length 3.4
  BOTTOM w0.254: U38.5 81.58,16.84 R138.1 R139.1
UNNAMED_12_ADLT8604_I100_RT: length 2.7
  BOTTOM w0.254: U38.8 77.94,18.02 R137.1
UNNAMED_12_ADLT8604_I100_SW: length 2.9
  BOTTOM w0.254: U38.10 80.19,19.02 79.75,19.46 77.77,19.46 L1.1
UNNAMED_12_ADLT8604_I100_SYNC: length 1.5
  BOTTOM w0.254: U38.7 79.63,17.52 R136.1
UNNAMED_12_ADLT8604_I100_TR: length 1.3
  BOTTOM w0.254: U38.6 81.08,16.09 C27.1
UNNAMED_12_ADP7182V3_I25_VOUT: length 4.9
  BOTTOM w0.508: U19.5 35.86,21.73 35.86,22.57 C119.1 32.24,22.57 JP25.3
UNNAMED_12_CAP_I88_N1: length 2.2
  BOTTOM w0.508: C28.1 31.54,17.19 JP24.3
UNNAMED_12_LINLT3045_I87_EN: length 2.6
  BOTTOM w0.254: R24.2 R77.2 U37.4
UNNAMED_12_LINLT3045_I87_ILIM: length 1.6
  BOTTOM w0.508: R135.1 U37.6
UNNAMED_12_LINLT3045_I87_SET: length 3.7
  BOTTOM w0.305: 33.85,15.15 33.92,15.21 33.92,15.23 R134.1 ; 33.85,15.15 33.74,15.03 33.74,14.68 33.87,14.55 C102.1 ; 33.85,15.15 U37.8
UNNAMED_13_ADA48072_I2_INV: length 2.8
  TOP w0.203: A5.6 53.24,7.59 53.4,7.43 53.4,7.14 53.2,6.94 A5.7
UNNAMED_13_ADA48072_I13_INV: length 3.1
  TOP w0.203: A5.2 58.28,6.94 C60.1 59.78,7.25 R49.1
UNNAMED_13_ADA48072_I13_NINV: length 1.9
  TOP w0.203: R48.2 57.66,7.59 A5.3
UNNAMED_13_ADA48072_I13_OUT: length 2.9
  TOP w0.203: R50.1 58.54,6.24 C60.2 56.85,6.29 A5.1
UNNAMED_13_ADA48072_I20_VS: length 1.6
  TOP w0.305: A5.8 R51.1
UNNAMED_13_ADA48072_I20_VS_1: length 2.1
  TOP w0.203: A5.4 57.21,8.24 R67.2
UNNAMED_13_ADA48971_I40_: length 1.7
  TOP w0.508: R149.2 66.22,22.97 U39.3
UNNAMED_13_ADA48971_I40__1: length 1.8
  TOP w0.508: R150.1 68.87,22.18 69.32,22.63 69.32,22.66 U39.4
UNNAMED_13_ADA48971_I40_OUT: length 5.7
  TOP w0.508: R151.1 R150.2 67.87,22.15 68.44,22.71 68.44,24.37 67.93,24.87 U39.1
UNNAMED_13_RES_I12_N1: length 2.9
  TOP w0.508: JP8.3 61.91,8.35 R86.1 R48.1
UNNAMED_13_RES_I17_N2: length 3.2
  TOP w0.203: R49.2 59.8,4.42 R87.1 R50.2
UNNAMED_13_RES_I28_N2: length 1.8
  TOP w0.203: R87.2 61.77,4.18 JP9.3
UNNAMED_13_RES_I29_N2: length 10.1
  TOP w0.508: R146.2 73.73,13.45 75.61,15.33 75.61,17.26 74.93,17.94 R147.2 73.12,19.35 JP1.2
UNNAMED_13_RESJMPR3P_I53_B: length 2
  TOP w0.508: JP2.3 71.86,21.31 JP1.1
UNNAMED_13_RESJMPRSHRT3P_I11_A: length 12.4
  TOP w0.508: JP8.1 68.05,6.74 68.51,6.28 68.51,3.05 68.17,2.71 JP9.1
VOCM: length 128.5
  TOP w0.254: C33.1 38.27,30.05 38.27,31.93 37.93,32.27 U3.9
  TOP w0.508: R30.1 38.27,28.14 v1(38.27,29.13) 38.27,29.99 C33.1 ; JP9.2 VOCM.1
  L4_GND w0.254: VOCM.1 62.6,8.88 39.16,8.88 35.54,12.49 32.43,12.49 31.16,13.76 ; 31.16,27.42 31.16,37.58 27.92,40.82 v1(27.92,41.83) ; 31.16,27.42 31.16,23.86 ; 31.16,27.42 31.73,27.42 33.95,29.64 37.76,29.64 v1(38.27,29.13) ; P1.4 11.34,31.2 11.34,19.71 11.35,19.71 11.35,19.64 17.23,13.76 31.16,13.76 ; 31.16,23.86 28.41,23.86 v1(28.18,24.09) ; 31.16,23.86 31.16,13.76
  BOTTOM w0.508: v1(27.92,41.83) JP7.3 ; C100.2 65.11,4.61 VOCM.1 ; v1(28.18,24.09) JP14.3
VTIN: length 14.6
  TOP w0.203: v1(60.7,58.55) 60.7,57.89 U30.20
  TOP w0.508: R120.1 R119.1 C120.1 65.15,49.59 65.65,50.09 v1(65.65,50.55)
  BOTTOM w0.203: 64.51,54.74 64.51,51.82 65.07,51.26 65.07,51.13 v1(65.65,50.55)
  BOTTOM w0.254: 64.51,54.74 v1(60.7,58.55)

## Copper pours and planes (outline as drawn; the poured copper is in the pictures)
5V_SUPP on TOP: 55.45,18.11 57.93,18.11 57.93,19.32 55.45,19.32
5V_SUPP on TOP: 71.23,24.43 71.23,22.08 73.52,22.08 73.52,24.43
5V_SUPP on TOP: 63.1,18.72 63.1,16.56 66.28,16.56 66.28,17 64.75,17 64.75,18.72
5V_SUPP on TOP: 63.23,12.56 63.23,10.65 64.56,10.65 64.56,11.99 66.47,11.99 66.47,12.56
5V_SUPP on TOP: 21.39,37.26 21.39,35.93 23.67,35.93 23.67,37.26
5V_SUPP on TOP: 35.47,27.93 35.47,27.18 35.36,27.07 35.36,26.16 35.43,26.1 36.44,26.1 36.51,26.16 36.51,26.99 36.28,27.22 36.28,27.93
5V_SUPP on TOP: 58.08,43.36 58.08,41.2 59.35,41.2 59.35,43.36
5V_SUPP on TOP: 58.08,29.07 58.08,26.91 59.35,26.91 59.35,29.07
5V_SUPP on TOP: 21.41,21.89 21.41,20.56 23.68,20.56 23.68,21.89
5V_SUPP on BOTTOM: 57.96,28.94 57.96,24.62 59.48,24.62 59.48,28.94
5V_SUPP on L3_PRIMARY_POWER: outline of 86 points within 22.46,3.99 73.83,43.67
5V_SUPP on L5_SECONDARY_POWER: 23.67,37.2 21.64,37.2 21.83,37.01 21.83,34.85 12.94,34.85 12.81,34.72 12.81,30.78 13,30.59 14.33,30.59 15.03,31.29 15.03,31.74 20.75,31.74 23.99,34.97 23.99,36.24 23.86,36.37 23.86,37.01
+3V3CLK on TOP: 83.41,57.66 81.41,57.66 81.33,57.75 81.33,58.53 81.2,58.66 79.55,58.66 79.48,58.6 79.48,56.34 79.62,56.2 81.4,56.2 81.53,56.32 81.53,56.83 81.72,57.02 83.28,57.02 83.41,57.15
+3V3CLK on TOP: 58.29,53.84 58.29,52.96 57,51.67 54.81,51.67 54.59,51.67 54.48,51.79 54.48,52.64 54.59,52.75 56.94,52.75 57.27,53.08 57.27,53.59 57.52,53.84
+3V3CLK on TOP: 58.29,55.84 57.57,55.84 57.4,56.01 57.4,56.23 57.7,56.53 58.29,56.53 58.29,56.84 57.33,56.84 56.78,56.29 54.93,56.29 54.85,56.37 54.85,56.88 54.34,56.88 54.34,55.53 58.29,55.53
+3V3CLK on TOP: 56.48,63.78 56.48,61.91 56.62,61.77 60.24,61.77 60.56,62.09 60.56,63.65 60.43,63.78
+3V3CLK on L5_SECONDARY_POWER: 53.4,63.82 66.86,63.82 66.86,60.58 66.92,60.44 67.05,60.39 81.72,60.39 81.72,56.07 78.42,56.07 78.42,58.29 78.36,58.43 78.23,58.48 65.21,58.48 65.21,60.71 65.15,60.84 65.02,60.9 62.61,60.9 62.47,60.84 62.42,60.71 62.42,52.7 62.47,52.57 62.61,52.51 64.96,52.51 64.96,49.72 53.4,49.72
+3V3FMC on TOP: 25.54,51.64 25.54,49.17 25.76,48.94 28.24,48.94 28.24,50.28 26.75,50.28 26.75,51.64
+3V3FMC on TOP: 11.51,51.71 11.51,49.23 11.73,49.01 14.27,49.01 14.27,50.47 12.71,50.47 12.71,51.71
+3V3FMC on TOP: 39.32,51.77 39.32,49.29 39.54,49.07 42.15,49.07 42.15,50.28 40.65,50.28 40.53,50.4 40.53,51.77
+3V3FMC on L3_PRIMARY_POWER: 104,46.55 104,46.55 104,0.64 40.18,0.64 40.18,4.37 40.94,5.13 49.58,5.13 51.35,3.35 52.31,3.35 54.08,5.13 74.47,5.13 76.12,6.78 76.12,10.72 80.69,10.72 80.69,6.92 88.44,6.92 88.44,13 85.58,13 84.06,14.53 82.6,14.53 81.71,15.42 81.71,18.27 83.99,18.27 83.99,16.18 97.14,16.18 97.14,12.94 97.52,12.56 100.19,12.56 100.88,13.26 100.88,26.16 100.71,26.34 100.84,26.39 100.9,26.53 100.9,61.64 43.35,61.64 43.35,59.55 42.34,59.55 42.21,59.68 42.21,61.26 41.83,61.64 40.88,61.64 40.88,49.26 40.56,48.94 39.48,48.94 39.29,49.13 39.29,61.2 38.84,61.64 27.22,61.64 27.22,52.75 28.49,51.48 29.07,51.48 29.07,48.82 27.54,48.82 25.89,50.47 25.89,61.64 16.11,61.64 16.11,61.58 16.05,61.64 14.84,61.64 14.81,61.61 13.79,61.61 13.06,60.88 13.06,49.01 11.79,49.01 11.16,49.64 11.16,66.85 11.7,67.39 12.71,67.39 12.75,67.42 104,67.42
+3V3VCCO on TOP: 62.34,57.03 63.25,57.03 63.99,57.77 64.66,57.77 64.66,60.11 64.51,60.26 63.43,60.26 63.3,60.13 63.3,58.99 63.11,58.8 62.29,58.8 62.04,58.56 62.04,57.33
+3V3VCCO on TOP: 83.41,51.88 81.41,51.88 81.32,51.98 81.32,52.37 79.43,52.37 79.43,50.61 79.43,50.61 79.43,49.96 81.53,49.96 81.53,51.05 81.72,51.24 83.28,51.24 83.41,51.37
+3V3VCCO on L5_SECONDARY_POWER: 62.8,60.52 64.83,60.52 64.83,58.29 64.88,58.16 65.02,58.1 66.73,58.1 66.73,56.26 66.79,56.13 66.92,56.07 68.26,56.07 68.26,52.2 68.31,52.06 68.45,52.01 80.89,52.01 80.89,50.48 80.13,50.48 80,50.43 79.94,50.29 79.94,49.72 65.34,49.72 65.34,52.7 65.28,52.84 65.15,52.9 62.8,52.9 ; 1 cut-out
+12V0FMC on BOTTOM: 83.36,19.73 83.36,18.84 84.31,18.84 84.31,16.56 86.22,16.56 86.22,19.73
+12V0FMC on BOTTOM: 39.54,18.4 39.54,16.18 45.19,16.18 45.19,14.4 45.51,14.08 48.05,14.08 48.05,18.4
+12V0FMC on L3_PRIMARY_POWER: 84.37,16.56 97.33,16.56 97.45,16.43 97.45,13.19 97.71,12.94 99.99,12.94 100.57,13.51 100.57,19.35 98.47,21.45 85.26,21.45 84.37,20.56
+12V0FMC on L5_SECONDARY_POWER: 104,61.07 104,0.64 97.72,0.64 97.72,56.07 89.64,56.07 89.64,54.91 86.66,54.91 86.66,56.06 86.64,56.07 86.34,56.07 86.34,61.07
+12V0FMC on L5_SECONDARY_POWER: 35.54,17 35.54,11.99 37.7,11.99 37.7,10.65 88.37,10.65 88.37,19.54 86.66,19.54 86.66,19.73 83.87,19.73 83.87,15.23 82.28,13.64 78.79,13.64 77.77,14.65 50.08,14.65 49.45,15.29 49.45,15.99 48.43,17
AGND on TOP: 0.64,68.36 51.39,68.36 51.39,68.36 104,68.36 104,0.64 87.55,0.64 87.12,0.64 0.64,0.64 0.64,20.46 0.08,20.46 0.08,30.88 0.64,30.88 0.64,35.16 0.08,35.16 0.08,45.58 0.64,45.58 ; 35 cut-outs
AGND on BOTTOM: 0.64,68.36 51.39,68.36 51.39,68.36 104,68.36 104,0.64 0.64,0.64 0.64,20.46 0.08,20.46 0.08,30.88 0.64,30.88 0.64,35.16 0.08,35.16 0.08,45.58 0.64,45.58 ; 30 cut-outs
AGND on L2_GND: 0.64,68.36 104,68.36 104,0.64 0.64,0.64 0.64,20.46 0.08,20.46 0.08,30.88 0.64,30.88 0.64,35.16 0.08,35.16 0.08,45.58 0.64,45.58
AGND on L3_PRIMARY_POWER: 100.71,46.93 100.57,46.87 100.52,46.74 100.52,26.72 87.23,26.72 87.23,31.37 73.4,31.37 73.21,31.56 73.21,35.55 72.05,35.55 72.05,37.45 72,37.58 71.86,37.64 69.77,37.64 69.77,43.61 65.51,43.61 65.32,43.8 65.32,61.71 66.02,61.01 100.38,61.01 100.71,60.68 ; 4 cut-outs
AGND on L3_PRIMARY_POWER: 0.64,50.61 5.52,50.61 5.52,20.62 7.67,20.62 7.67,0.64 0.64,0.64 0.64,20.46 0.08,20.46 0.08,30.88 0.64,30.88 0.64,35.16 0.08,35.16 0.08,45.58 0.64,45.58
AGND on L4_GND: 0.64,68.36 104,68.36 104,0.64 0.64,0.64 0.64,20.46 0.08,20.46 0.08,30.88 0.64,30.88 0.64,35.16 0.08,35.16 0.08,45.58 0.64,45.58 0.64,50.67 0.63,50.67 0.63,61.09 0.64,61.09
AGND on L5_SECONDARY_POWER: 0.64,68.36 51.39,68.36 51.39,68.36 104,68.36 104,0.64 87.55,0.64 87.12,0.64 0.64,0.64 0.64,20.46 0.08,20.46 0.08,30.88 0.64,30.88 0.64,35.16 0.08,35.16 0.08,45.58 0.64,45.58 ; 35 cut-outs
AVDD11 on TOP: 67.36,38.47 67.36,36.18 67.93,36.18 67.93,35.48 65.2,35.48 65.2,38.47
AVDD11 on BOTTOM: 66.63,35.48 66.63,38.43 65.2,38.43 65.2,35.48
AVDD11 on L3_PRIMARY_POWER: 60.64,38.53 66.61,38.53 66.61,36.96 66.03,36.96 65.9,36.9 65.84,36.77 65.84,35.37 64.7,35.37 64.57,35.31 64.51,35.18 64.51,28.12 60.64,28.12
AVDD11 on L5_SECONDARY_POWER: 63.16,40.94 63.16,35.61 65.77,35.61 65.77,36.82 66.72,36.82 66.72,40.94
DVDD11 on TOP: 68.19,35.48 68.19,36.37 67.55,36.37 67.55,38.47 68.56,38.47 68.56,35.48
DVDD11 on BOTTOM: 70.09,41.13 70.09,37.89 70.85,37.89 70.85,38.59 71.04,38.59 71.04,41.13
DVDD11 on BOTTOM: 66.96,38.43 66.96,35.48 68.12,35.48 68.12,38.43
DVDD11 on L5_SECONDARY_POWER: 66.91,40.94 66.91,36.37 68.88,36.37 68.88,38.21 71.1,38.21 71.1,40.94
VDDAFE_U1 on TOP: 20.56,37.26 20.56,35.93 19.21,35.93 19.21,37.39 18.21,37.39 18.21,38.66 20.24,38.66 20.24,37.26
VDDCR11 on TOP: 30.18,59.36 30.18,57.04 31.38,57.04 31.38,59.36
VDDCR11 on TOP: 21.16,57.74 21.16,55.26 22.37,55.26 22.37,57.74
VDDCR11 on BOTTOM: 22.84,58.53 22.27,57.96 22.27,56.37 21.32,56.37 21.13,56.56 21.13,58.91 21.51,59.29 31.61,59.29 31.61,57.26 31.35,57.01 30.4,57.01 29.95,57.45 29.95,58.47 26.14,58.47 26.08,58.53
VDDCR11 on L5_SECONDARY_POWER: 30.02,58.34 30.02,46.78 35.16,41.64 52.62,41.64 55.54,44.56 61.83,44.56 62.91,43.48 62.91,41.45 63.1,41.26 65.51,41.26 65.83,41.58 65.83,46.66 50.85,46.66 48.81,44.63 38.21,44.63 33.13,49.71 33.13,56.82 31.41,58.53 30.21,58.53
VDDDRV_A1 on TOP: 54.97,40.88 54.97,40.05 59.35,40.05 59.35,40.88
VDDDRV_A6 on TOP: 54.97,26.59 54.97,25.77 59.35,25.77 59.35,26.59
VDDIO11 on TOP (solid shape): 80.74,37.05 81.13,37.05 81.13,36.54 80.73,36.54 80.48,36.29 80.1,36.29 79.98,36.42 79.98,37.24 80.04,37.31 80.49,37.31
VDDIO11 on TOP (solid shape): 80.74,29.18 81.13,29.18 81.13,28.68 80.73,28.68 80.48,28.43 80.1,28.43 79.98,28.55 79.98,29.38 80.04,29.44 80.49,29.44
VDDIO11 on TOP (solid shape): 80.74,25.51 81.13,25.51 81.13,25 80.73,25 80.48,24.75 80.1,24.75 79.98,24.88 79.98,25.7 80.04,25.77 80.49,25.77
VDDIO11 on TOP (solid shape): 80.74,21.83 81.13,21.83 81.13,21.32 80.73,21.32 80.48,21.07 80.1,21.07 79.98,21.2 79.98,22.02 80.04,22.09 80.49,22.09
VDDIO11 on BOTTOM (solid shape): 80.74,44.4 81.13,44.4 81.13,43.9 80.73,43.9 80.48,43.65 80.1,43.65 79.98,43.77 79.98,44.6 80.04,44.66 80.49,44.66
VDDIO11 on BOTTOM (solid shape): 80.74,37.05 81.13,37.05 81.13,36.54 80.73,36.54 80.48,36.29 80.1,36.29 79.98,36.42 79.98,37.24 80.04,37.31 80.49,37.31
VDDIO11 on BOTTOM (solid shape): 80.74,29.18 81.13,29.18 81.13,28.68 80.73,28.68 80.48,28.43 80.16,28.43 79.98,28.61 79.98,29.38 80.04,29.44 80.49,29.44
VDDIO11 on BOTTOM (solid shape): 80.74,25.51 81.13,25.51 81.13,25 80.73,25 80.48,24.75 80.1,24.75 79.98,24.88 79.98,25.7 80.04,25.77 80.49,25.77
VDDIO11 on BOTTOM (solid shape): 80.74,21.83 81.13,21.83 81.13,21.32 80.73,21.32 80.48,21.07 80.1,21.07 79.98,21.2 79.98,22.02 80.04,22.09 80.49,22.09
VDDIO11 on TOP: 40.53,59.36 40.53,57.1 41.73,57.1 41.73,59.36
VDDIO11 on TOP: 49.07,54.88 51.32,54.88 51.32,56.09 49.07,56.09
VDDIO11 on TOP, BOTTOM: 81.13,40.22 80.78,40.22 80.53,39.96 79.78,39.96 79.61,40.12 79.61,40.44 79.84,40.68 81.13,40.68
VDDIO11 on TOP, BOTTOM: 81.13,44.4 80.74,44.4 80.49,44.66 80.04,44.66 79.98,44.6 79.98,43.77 80.1,43.65 80.48,43.65 80.73,43.9 81.13,43.9
VDDIO11 on TOP, BOTTOM: 81.13,33.37 80.78,33.37 80.53,33.63 79.78,33.63 79.61,33.46 79.61,33.15 79.84,32.91 81.13,32.91
VDDIO11 on L5_SECONDARY_POWER: outline of 109 points within 40.37,20.69 92.44,61.52
VDDLDO on L3_PRIMARY_POWER: 64.83,48.05 64.83,43.85 65.45,43.23 69.45,43.23 69.45,34.73 67.99,34.73 67.99,38.4 67.42,38.97 67.42,40.63 67.29,40.75 62.34,40.75 61.13,41.96 61.13,44.24 44.75,44.24 44.37,44.63 44.37,47.36 45.07,48.05 52.31,48.05 52.31,58.53 51.61,58.53 50.53,59.61 50.53,60.63 51.16,61.26 52.31,61.26 52.31,61.52 52.37,61.45 54.08,61.45 54.08,48.25 53.89,48.05
VSSAFE on TOP: 54.15,44.63 54.15,43.04 56.94,43.04 56.94,44.63
VSSAFE on TOP: 18.91,29.19 18.65,28.93 18.65,28.05 18.91,27.79 20.73,27.79 20.99,28.05 20.99,28.88 20.68,29.19
VSSAFE on TOP: 18.92,44.43 18.65,44.16 18.65,43.3 18.92,43.03 20.74,43.03 21,43.29 21,44.12 20.69,44.43
VSSAFE on TOP: 54.15,30.4 54.15,28.81 56.94,28.81 56.94,30.4
VSSAFE on TOP: 49.32,34.47 49.32,33.45 51.67,33.45 51.67,34.47
VSSAFE on TOP: 49.33,20.18 49.33,19.16 51.68,19.16 51.68,20.18
VSSAFE on TOP: 35.47,38.09 35.47,38.93 35.36,39.03 35.36,39.94 35.43,40.01 36.44,40.01 36.51,39.94 36.51,39.12 36.28,38.88 36.28,38.09
VSSAFE on BOTTOM: 53.58,45.2 53.58,42.4 56.88,42.4 56.88,45.2
VSSAFE on L3_PRIMARY_POWER: 29.19,10.24 24.52,10.24 24.49,10.21 19.41,10.21 19.16,10.46 19.16,44.75 21.32,44.75 22.08,43.99 22.08,13.32 23.16,12.24 24.24,12.24 25.32,13.32 25.32,18.4 27.86,18.4 28.75,17.51 30.02,17.51 30.72,18.21 30.72,19.42 28.72,21.42 28.72,37.48 31.35,40.12 37.89,40.12 38.65,39.36 38.65,38.72 36.81,36.88 36.81,28.31 36.21,27.7 33.67,27.7 33.07,27.1 33.07,24.88 33.67,24.27 36.08,24.27 40.88,19.48 47.23,19.48 49.58,21.83 49.58,36.24 49.77,36.43 51.16,36.43 52.31,35.29 52.31,16.3 50.46,14.46 33.32,14.46 31.8,12.94 31.8,12.84
VSSAFE on L5_SECONDARY_POWER: 56.78,44.28 57.13,43.93 57.13,29.26 56.62,28.75 55.86,28.75 55.42,29.2 55.42,32.94 55.1,33.26 50.91,33.26 50.66,33.51 50.66,34.4 50.85,34.59 55.1,34.59 55.29,34.78 55.29,43.67 55.89,44.28
VSSAFE on L5_SECONDARY_POWER: 21.06,27.8 21.38,28.12 21.38,28.94 20.75,29.58 12.75,29.58 12.43,29.89 12.43,38.15 11.41,38.15 10.71,37.45 10.71,28.69 11.6,27.8
VSSAFE_U1 on TOP: 16.56,44.44 16.56,42.02 17.83,42.02 17.83,44.44
VSSAFE_U2 on TOP: 16.55,29.2 16.55,26.78 17.82,26.78 17.82,29.2
VSSDRV_A1 on TOP: 49.32,38.28 49.32,34.85 50.53,34.85 50.53,37.01 56.56,37.01 56.56,38.28
VSSDRV_A6 on TOP: 49.32,23.99 49.32,20.56 50.53,20.56 50.53,22.72 56.56,22.72 56.56,23.99
(no net) on TOP: 81.13,42.63 80.78,42.63 80.53,42.89 79.78,42.89 79.61,42.72 79.61,42.4 79.84,42.17 81.13,42.17
(no net) on TOP, BOTTOM: 81.13,27.41 80.74,27.41 80.49,27.67 80.04,27.67 79.98,27.6 79.98,26.78 80.1,26.65 80.48,26.65 80.73,26.9 81.13,26.9
(no net) on TOP, BOTTOM: 81.13,25.51 80.74,25.51 80.49,25.77 80.04,25.77 79.98,25.7 79.98,24.88 80.1,24.75 80.48,24.75 80.73,25 81.13,25
(no net) on TOP, BOTTOM: 81.13,21.83 80.74,21.83 80.49,22.09 80.04,22.09 79.98,22.02 79.98,21.2 80.1,21.07 80.48,21.07 80.73,21.32 81.13,21.32
(no net) on TOP, BOTTOM: 81.13,23.73 80.74,23.73 80.49,23.99 80.04,23.99 79.98,23.92 79.98,23.1 80.1,22.97 80.48,22.97 80.73,23.22 81.13,23.22
(no net) on TOP, BOTTOM: 81.13,29.18 80.74,29.18 80.49,29.44 80.04,29.44 79.98,29.38 79.98,28.55 80.1,28.43 80.48,28.43 80.73,28.68 81.13,28.68
(no net) on TOP, BOTTOM: 81.13,38.95 80.74,38.95 80.49,39.21 80.04,39.21 79.98,39.14 79.98,38.32 80.1,38.19 80.48,38.19 80.73,38.44 81.13,38.44
(no net) on TOP, BOTTOM: 81.13,37.05 80.74,37.05 80.49,37.31 80.04,37.31 79.98,37.24 79.98,36.42 80.1,36.29 80.48,36.29 80.73,36.54 81.13,36.54
(no net) on BOTTOM: 81.13,44.4 80.74,44.4 80.49,44.66 80.04,44.66 79.98,44.6 79.98,43.77 80.1,43.65 80.48,43.65 80.73,43.9 81.13,43.9
EXT_5V on TOP: 25.06,10.34 25.06,2.02 29.13,2.02 29.13,6.27 28.56,6.27 28.56,10.34
EXT_5V on L5_SECONDARY_POWER: 24.81,15.8 24.81,7.92 29.57,7.92 29.57,15.8
EXT_M2V5 on TOP: 32.43,1.95 35.61,1.95 35.61,7.73 36.88,7.73 36.88,10.4 33.83,10.4 33.83,6.27 32.43,6.27
EXT_M2V5 on L5_SECONDARY_POWER: 28.81,16.18 32.11,16.18 32.11,7.86 37.13,7.86 37.13,11.61 35.03,11.61 35.03,20.37 28.81,20.37
EXT_VDD1V1 on TOP: 29.89,63.68 29.89,61.52 29.64,61.26 27.8,61.26 27.67,61.14 27.67,60.31 27.86,60.12 31.41,60.12 31.54,60.25 31.54,63.68
EXT_VDD3V3 on TOP: 41.83,9.13 41.83,2.97 44.75,2.97 44.75,9.13
